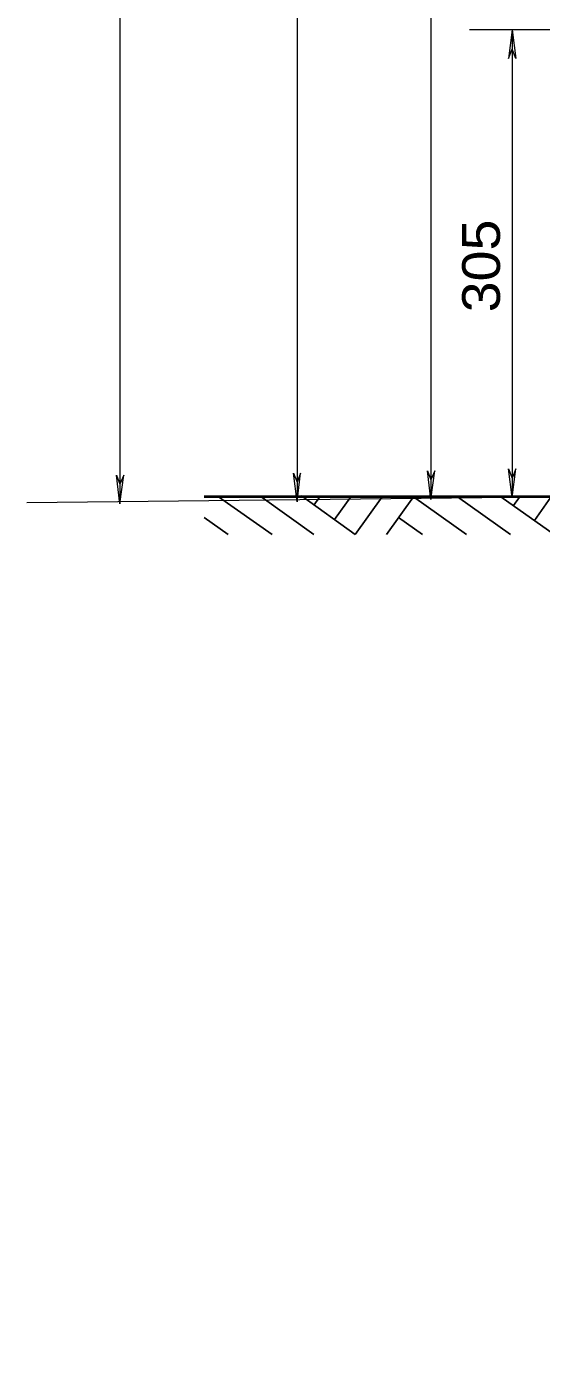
# Model space of a CAD drawing. Extents: x 312583 to 312854, y 144419 to 144597.
# Drawn here: x 312798.72 to 312809.06, y 144489.44 to 144516.42 of the extents above; entities that cross this region are included whole.
import ezdxf

# ---------------------------------------------------------------- set-up
doc = ezdxf.new("R2010")
doc.units = 0
doc.header["$LTSCALE"] = 0.3
doc.layers.add('1', color=7, linetype='Continuous', lineweight=40)
doc.layers.add('2', color=7, linetype='Continuous', lineweight=13)

msp = doc.modelspace()

# ---------------------------------------------------------------- linework, layer by layer
at = {"layer": '1'}
msp.add_line((312810.0565, 144506.9643), (312802.2825, 144506.9643), dxfattribs=at)
msp.add_line((312810.0565, 144506.9643), (312802.2825, 144506.9643), dxfattribs=at)
msp.add_line((312810.0565, 144506.9643), (312802.2825, 144506.9643), dxfattribs=at)
msp.add_line((312810.0565, 144506.9643), (312802.2825, 144506.9643), dxfattribs=at)
at = {"layer": '1', "lineweight": 25}
for p, q in [((312810.0565, 144506.9643), (312802.2825, 144506.9643)), ((312803.6472, 144506.2053), (312802.5738, 144506.9643)), ((312804.4905, 144506.2053), (312803.4478, 144506.9489)), ((312805.3185, 144506.2053), (312804.2375, 144506.9796)), ((312804.6055, 144506.9643), (312804.4905, 144506.7956)), ((312805.2342, 144506.9643), (312804.9045, 144506.5043)), ((312805.8628, 144506.9643), (312805.3185, 144506.2053)), ((312806.4915, 144506.9643), (312805.9472, 144506.2053)), ((312807.5572, 144506.2053), (312806.4915, 144506.9643)), ((312808.4388, 144506.2053), (312807.3732, 144506.9643)), ((312809.3205, 144506.2053), (312808.2472, 144506.9643)), ((312808.6228, 144506.9566), (312808.5002, 144506.7879)), ((312809.2515, 144506.9566), (312808.9218, 144506.4889)), ((312802.7655, 144506.2053), (312802.2825, 144506.5503)), ((312806.6755, 144506.2053), (312806.1925, 144506.5503))]:
    msp.add_line(p, q, dxfattribs=at)
for points in [[(312802.2825, 144506.9643), (312810.0565, 144506.9643), (312810.0335, 144507.9456)], [(312802.2825, 144506.9643), (312810.0565, 144506.9643), (312809.9185, 144489.4383)], [(312802.2825, 144506.9643), (312810.0565, 144506.9643), (312809.9185, 144489.4383)], [(312802.2825, 144506.9643), (312810.0565, 144506.9643), (312810.0028, 144498.6689), (312809.9185, 144489.4383)]]:
    msp.add_lwpolyline(points, dxfattribs=at)
at = {"layer": '2'}
for p, q in [((312800.5894, 144570.0456), (312800.5894, 144506.8186)), ((312804.153, 144541.5639), (312804.153, 144506.8646)), ((312806.8427, 144537.6463), (312806.8427, 144506.9106)), ((312813.1538, 144516.3559), (312807.6185, 144516.3559)), ((312808.4772, 144516.3559), (312808.4005, 144515.7809)), ((312808.4772, 144516.3559), (312808.4005, 144515.7809)), ((312808.4772, 144516.3559), (312808.4772, 144506.9489)), ((312808.4772, 144516.3559), (312808.5462, 144515.7809)), ((312808.4772, 144516.3559), (312808.5462, 144515.7809)), ((312808.4005, 144515.7809), (312808.4772, 144515.9649)), ((312808.4005, 144515.7809), (312808.4772, 144515.9649)), ((312808.5462, 144515.7809), (312808.4772, 144515.9649)), ((312808.5462, 144515.7809), (312808.4772, 144515.9649)), ((312806.7737, 144507.4856), (312806.8427, 144507.3016)), ((312806.8427, 144506.9106), (312806.7737, 144507.4856)), ((312806.9194, 144507.4856), (312806.8427, 144507.3016)), ((312806.8427, 144506.9106), (312806.9194, 144507.4856)), ((312808.4005, 144507.5239), (312808.4772, 144507.3399)), ((312808.4772, 144506.9489), (312808.4005, 144507.5239)), ((312808.5462, 144507.5239), (312808.4772, 144507.3399)), ((312808.4772, 144506.9489), (312808.5462, 144507.5239)), ((312800.5204, 144507.4013), (312800.5894, 144507.2173)), ((312800.5894, 144506.8186), (312800.5204, 144507.4013)), ((312800.6661, 144507.4013), (312800.5894, 144507.2173)), ((312800.5894, 144506.8186), (312800.6661, 144507.4013)), ((312804.0763, 144507.4396), (312804.153, 144507.2556)), ((312804.153, 144506.8646), (312804.0763, 144507.4396)), ((312804.222, 144507.4396), (312804.153, 144507.2556)), ((312804.153, 144506.8646), (312804.222, 144507.4396)), ((312808.4772, 144506.9489), (312798.7188, 144506.8429))]:
    msp.add_line(p, q, dxfattribs=at)

# ---------------------------------------------------------------- texts
at = {"layer": '2', "width": 1.1}
msp.add_text('305', height=0.76, rotation=90, dxfattribs=at).set_placement((312808.2295, 144510.6733))

doc.saveas('drawing.dxf')
